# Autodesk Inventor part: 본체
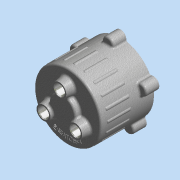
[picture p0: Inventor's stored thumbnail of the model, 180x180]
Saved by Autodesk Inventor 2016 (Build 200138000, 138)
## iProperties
Created: 2015-11
Part Number: 본체
Document SubType Name: 모델링
Designer: mdu
Material: 알루미늄 6061
Density: 2.71 g/cm^3
Appearance: 알루미늄 - 평지
Mass: 488.468 g
Surface Area: 697.01 cm^2
Volume: 180.247 cm^3
변환 표준: STEP AP214IS
파일 이름: C:\Users\SeoGD\Desktop\?쒗뿕\紐몄껜.stp
전처리기: Build: 253, Release: 2010 SP1 - Date: Wed 07/29/2009
전송 단위: 밀리미터
불확실성: 0.01
Author: mdu
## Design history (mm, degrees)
sketch "스케치2"
  geometry: C1 r 50 at (0, 0); 1 further point
  constraints: 1 centre point, 1 coincident
  dimensions: "d9" = 100 diameter of C1
extrude "돌출2" new body sketch "스케치2" distance "d10" = 80; taper "d11" = 0 deg
feature "쉘1" dims "d12" = 5
sketch "스케치3" dims "d13" = 55
  geometry: C1 r 7.5 at (0, 27.5); C2 r 12.5 at (0, 27.5); 2 further points
  constraints: 2 centre point, 2 coincident, 2 vertical alignment, 2 other
  dimensions: "d14" = 15 diameter of C1; "d15" = 25 diameter of C2
extrude "돌출3" join sketch "스케치3" distance "d16" = 12; taper "d17" = -10 deg
hole "구멍2" diameter "d20" = 15; stored, may be unused: countersink angle "d24" = 90 deg, drill point angle "d26" = 118 deg; dims "d18" = 10, "d19" = 10, "d21" = 6, "d22" = 4, "d23" = 2, "d25" = 15
chamfer "모따기1" distance "d27" = 1; stored, may be unused: second distance "d28" = 2, angle "d29" = 45 deg
sketch "스케치4"
  geometry: L1 (0, 0)-(0, 88); L2 (0, 70)-(13.16, 70); L3 (-45, 75)-(45, 75) reference; L4 (-50, 80)-(50, 80) reference; L5 (13.16, 70)-(14.5, 75); L6 (20, 80)-(20, 88); L7 (20, 88)-(0, 88); L8 (20, 80)-(14.5, 75)
  constraints: 12 end point, 3 point on line, 2 perpendicular, 1 vertical
  dimensions: "d34" = 40 diameter of L6 L1; "d35" = 105 deg angle of L5 L3; "d36" = 5 distance between parallel lines of L2 L3; "d37" = 8 distance between parallel lines of L7 L4; "d51" = 29 diameter of L5.end L1
revolve "회전1" sketch "스케치4" stored, may be unused: angle "d38" = 90 deg
hole "구멍3" diameter "d41" = 15; stored, may be unused: countersink angle "d45" = 90 deg, drill point angle "d47" = 0 deg; dims "d39" = 10, "d40" = 10, "d42" = 6, "d43" = 22, "d44" = 13, "d46" = 15
chamfer "모따기2" distance "d48" = 1; stored, may be unused: second distance "d49" = 2, angle "d50" = 45 deg
fillet "모깎기1" dims "d52" = 3
fillet "모깎기2" dims "d53" = 3, "d72" = 0.2
sketch "스케치5"
  geometry: A1 r 50 centre (0, 0) between (50, 0) and (-8.074, 49.344) reference; A2 r 8.5 centre (0, 52) between (8.074, 49.344) and (-8.074, 49.344); 1 further point
  constraints: 5 point on circle, 1 centre point, 1 horizontal alignment
  dimensions: "d54" = 90 deg dimension on point (0, 0) A2.centre A1.start; "d55" = 52 distance of A2.centre point (0, 0); "d56" = 17 diameter of A2
extrude "돌출4" join sketch "스케치5" distance "d57" = 20; taper "d58" = 0 deg
fillet "모깎기3" dims "d59" = 3
hole "구멍4" diameter "d62" = 4.134; stored, may be unused: countersink angle "d66" = 90 deg, drill point angle "d68" = 118 deg; dims "d60" = 10, "d61" = 10, "d63" = 12, "d64" = 22, "d65" = 13, "d67" = 15
sketch "스케치6"
  geometry: C1 r 47 at (0, 0) reference; C2 r 42.5 at (0, 0); 1 further point
  constraints: 1 centre point, 1 coincident, 1 other
  dimensions: "d73" = 85 diameter of C2
feature "엠보싱1" sketch "스케치6" dims "d74" = 0.5, "d75" = 0
node "작업 평면1"
sketch "스케치7"
  geometry: A1 r 50 centre (0, 0) between (5.144, 49.735) and (-5.144, 49.735) reference; A2 r 3 centre (0, 47.916) between (2.204, 49.951) and (-2.204, 49.951); 1 further point
  constraints: 4 point on circle, 1 centre point, 1 vertical alignment
  dimensions: "d77" = 3 radius of A2
extrude "돌출5" join sketch "스케치7" distance "d79" = 35; taper "d80" = 0 deg
fillet "모깎기4" dims "d81" = 1
fillet "모깎기5" dims "d82" = 1
node "솔리드1"
node "솔리드 본체"
node "곡면 본체"
pattern_circular "원형 패턴1" dims "d31" = 360 deg
pattern_circular "원형 패턴2" dims "d70" = 360 deg
pattern_circular "원형 패턴3" dims "d84" = 360 deg
node "솔리드2"
